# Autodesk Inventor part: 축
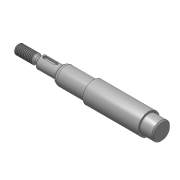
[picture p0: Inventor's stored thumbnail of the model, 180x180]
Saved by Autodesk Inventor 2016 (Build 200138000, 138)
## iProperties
Created: 2015-11
Part Number: 축
Material: 강철, 연강
Document SubType Name: Modeling
Designer: mduedu
Density: 1 g/cm^3
Appearance: 강철
Author: mduedu
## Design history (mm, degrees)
sketch "스케치1"
  geometry: L1 (-86, 0)-(86, 0); L2 (-86, 0)-(-86, 4); L3 (-86, 4)-(-70.732, 4); L4 (-70.732, 4)-(-69, 3); L5 (-69, 3)-(-67, 3); L6 (-67, 3)-(-67, 5); L7 (-67, 5)-(-49, 5); L8 (-49, 5)-(-49, 6.55); L9 (-47.355, 7.5)-(-23, 7.5); L10 (-23, 7.5)-(-23, 9); L11 (0, 0)-(0, 9); L12 (86, 4)-(70.732, 4); L13 (70.732, 4)-(69, 3); L14 (69, 3)-(67, 3); L15 (67, 3)-(67, 5); L16 (67, 5)-(49, 5); L17 (23, 7.5)-(23, 9); L18 (86, 0)-(86, 4); L19 (-23, 9)-(23, 9); L20 (-49, 6.55)-(-47.355, 7.5); L21 (47.355, 7.5)-(23, 7.5); L22 (49, 6.55)-(47.355, 7.5); L23 (49, 5)-(49, 6.55); 1 further point
  constraints: 46 end point, 10 symmetric about line, 6 perpendicular, 5 parallel, 2 midpoint, 1 coincident, 1 horizontal
  dimensions: "d0" = 172 distance of L1.start L1.end (derived); "d1" = 8 diameter of L3 L1; "d2" = 30 deg angle of L4 L5; "d3" = 6 diameter of L5 L1; "d4" = 10 diameter of L7 L1; "d5" = 15 diameter of L9 L1; "d6" = 18 diameter of L19 L1; "d8" = 18 distance of L6.end L7.end; "d9" = 46 distance of L10.end L17.end; "d10" = 2 distance of L4.end L5.end; "d11" = 17 distance from line of L4.end L2; "d16" = 13.1 diameter of L8.end L1; "d17" = 30 deg angle of L20 L9; "d18" = 26 distance between parallel lines of L10 L8
revolve "회전1" sketch "스케치1" stored, may be unused: angle "d12" = 90 deg
chamfer "모따기1" distance "d13" = 1; stored, may be unused: second distance "d14" = 2, angle "d15" = 45 deg
fillet "모깎기3" dims "d35" = 4
node "작업 평면1"
sketch "스케치2" dims "d23" = 12
  geometry: L1 (-5.5, 1.5)-(3.5, 1.5); L2 (3.5, 1.5)-(3.5, -1.5); L3 (3.5, -1.5)-(-5.5, -1.5); L4 (-5.5, -1.5)-(-5.5, 1.5); L5 (-9, -4)-(-9, 4) reference; 3 further points
  constraints: 8 end point, 2 midpoint, 2 parallel, 2 vertical alignment, 1 horizontal, 1 perpendicular, 4 other
  dimensions: "d21" = 3 distance between parallel lines of L3 L1; "d24" = 2 dimension on L5
extrude "돌출1" cut sketch "스케치2" distance "d25" = 1.8; taper "d26" = 0 deg
feature "스레드1" dims "d27" = 10, "d28" = 0
feature "스레드2" dims "d29" = 10, "d30" = 0
chamfer "모따기2" distance "d31" = 1; stored, may be unused: second distance "d32" = 2, angle "d33" = 45 deg
fillet "모깎기2" dims "d34" = 0.3
node "작업 평면2"
sketch "스케치3"
  geometry: C1 r 7.5 at (0, 0) reference; 1 further point
extrude "돌출2" cut sketch "스케치3" stored distance "d37" = 10; taper "d38" = 0 deg
chamfer "모따기3" distance "d39" = 1; stored, may be unused: second distance "d40" = 2, angle "d41" = 45 deg
node "솔리드1"
mirror "대칭1"
node "절단 모서리 투영1"
other parameters: "d36" = 11
